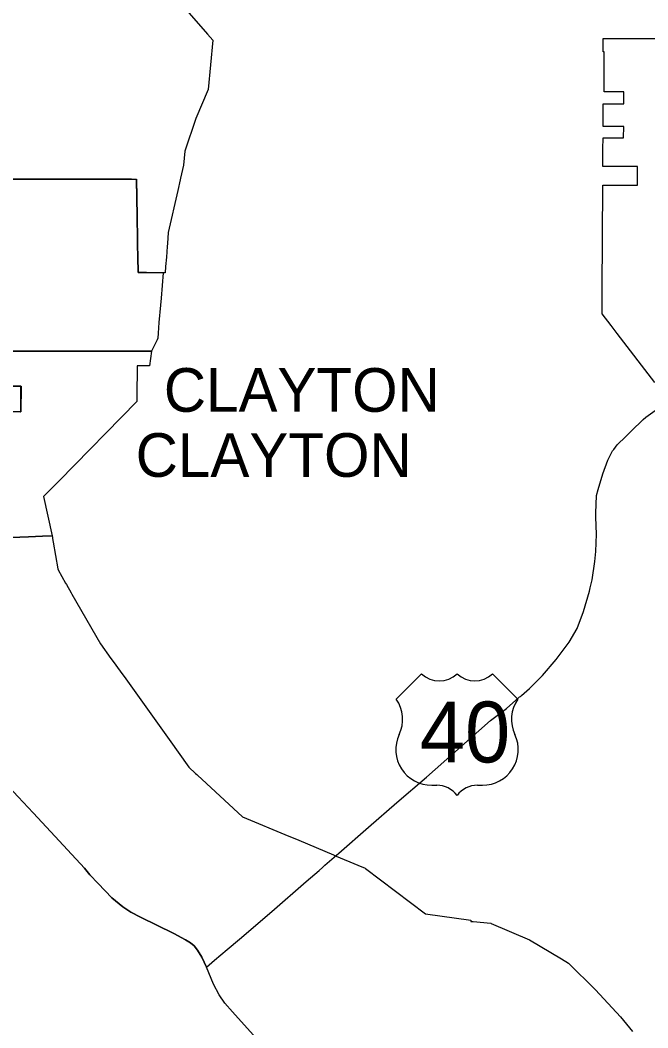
# Model space of a CAD drawing. Extents: x 0 to 34, y 0 to 22.
# Drawn here: x 4.8367 to 4.9522, y 15.7932 to 15.9787 of the extents above; entities that cross this region are included whole.
import ezdxf

# ---------------------------------------------------------------- set-up
doc = ezdxf.new("R2010")
doc.units = 0
for name, color, linetype in [('GM_X_Corporation', 7, 'Continuous'), ('GM_X_Corporation_Text', 7, 'Continuous'), ('GM_X_State_Route', 7, 'Continuous'), ('GM_X_US_Location', 7, 'Continuous'), ('GM_X_US_Route', 7, 'Continuous'), ('GM_X_US_Shield', 7, 'Continuous')]:
    doc.layers.add(name, color=color, linetype=linetype)

msp = doc.modelspace()

# ---------------------------------------------------------------- linework, layer by layer
at = {"layer": 'GM_X_Corporation'}
for points in [[(4.86732801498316, 15.98048374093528), (4.870376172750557, 15.977005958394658), (4.871194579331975, 15.976072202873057), (4.872133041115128, 15.975001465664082), (4.871292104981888, 15.965905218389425), (4.869025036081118, 15.960558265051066), (4.867015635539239, 15.954570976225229), (4.866730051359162, 15.951961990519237), (4.866198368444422, 15.949594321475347), (4.866121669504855, 15.949252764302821), (4.865683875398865, 15.94730306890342), (4.863947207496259, 15.939568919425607), (4.863789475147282, 15.937548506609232), (4.863745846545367, 15.936989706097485), (4.863596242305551, 15.935073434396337), (4.863461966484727, 15.93335351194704), (4.863369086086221, 15.93216379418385), (4.863229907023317, 15.932165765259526), (4.863014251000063, 15.932168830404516), (4.859974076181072, 15.93221248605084), (4.858384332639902, 15.932235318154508), (4.858335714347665, 15.935125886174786), (4.858325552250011, 15.935730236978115), (4.858309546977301, 15.936681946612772), (4.858282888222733, 15.938266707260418), (4.858210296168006, 15.942582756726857), (4.858096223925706, 15.94936529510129), (4.857178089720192, 15.949367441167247), (4.857005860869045, 15.949367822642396), (4.842103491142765, 15.949400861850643), (4.835353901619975, 15.949415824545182)], [(4.953444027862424, 15.912000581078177), (4.946545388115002, 15.920981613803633), (4.945430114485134, 15.922445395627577), (4.943764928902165, 15.92463092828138), (4.943765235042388, 15.924695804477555), (4.943779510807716, 15.927757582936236), (4.943785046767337, 15.928945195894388), (4.943875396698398, 15.94832243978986), (4.950272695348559, 15.94831126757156), (4.950289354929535, 15.951703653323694), (4.94389204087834, 15.951711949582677), (4.943907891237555, 15.954940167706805), (4.943917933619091, 15.956984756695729), (4.947715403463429, 15.956991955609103), (4.947723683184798, 15.959090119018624), (4.943928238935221, 15.95908292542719), (4.94393893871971, 15.961261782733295), (4.943948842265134, 15.963279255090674), (4.944113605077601, 15.963279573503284), (4.947731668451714, 15.96328642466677), (4.947740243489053, 15.963286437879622), (4.9477403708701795, 15.963318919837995), (4.947748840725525, 15.965465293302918), (4.944124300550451, 15.965458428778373), (4.94413105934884, 15.966834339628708), (4.944134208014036, 15.967475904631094), (4.9441441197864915, 15.969493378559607), (4.944120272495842, 15.972834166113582), (4.943975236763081, 15.972833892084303), (4.943964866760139, 15.975254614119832), (4.946785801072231, 15.97525996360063), (4.9477874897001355, 15.975261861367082), (4.9506039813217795, 15.975267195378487), (4.965187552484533, 15.975300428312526)], [(4.835353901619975, 15.949415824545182), (4.842103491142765, 15.949400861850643), (4.857005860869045, 15.949367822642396), (4.857178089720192, 15.949367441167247), (4.858096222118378, 15.949365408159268), (4.858210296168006, 15.942582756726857), (4.858282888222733, 15.938266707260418), (4.858309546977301, 15.936681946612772), (4.858325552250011, 15.935730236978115), (4.858335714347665, 15.935125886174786), (4.858384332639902, 15.932235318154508), (4.859974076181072, 15.93221248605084), (4.863014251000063, 15.932168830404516), (4.862641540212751, 15.927490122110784), (4.862538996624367, 15.926202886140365), (4.862204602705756, 15.923007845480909), (4.862080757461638, 15.921040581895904), (4.862022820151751, 15.920120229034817), (4.8618837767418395, 15.919837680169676), (4.86140467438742, 15.91886410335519), (4.860857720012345, 15.917752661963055), (4.85820128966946, 15.917755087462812), (4.854761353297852, 15.917758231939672), (4.838647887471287, 15.917772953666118), (4.836753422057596, 15.917774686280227), (4.834143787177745, 15.917777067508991)], [(4.834143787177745, 15.917777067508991), (4.836753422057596, 15.917774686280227), (4.838647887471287, 15.917772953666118), (4.854761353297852, 15.917758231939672), (4.85820128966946, 15.917755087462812), (4.860857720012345, 15.917752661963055), (4.8605043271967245, 15.91503645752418), (4.858202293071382, 15.915058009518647), (4.858149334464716, 15.909350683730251), (4.858146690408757, 15.909060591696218), (4.8581415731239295, 15.908499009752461), (4.843850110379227, 15.893888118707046), (4.841019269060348, 15.890994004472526), (4.842564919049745, 15.883763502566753), (4.840817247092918, 15.883692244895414), (4.838247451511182, 15.88358746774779), (4.833542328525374, 15.883395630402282)], [(4.833394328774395, 15.91131844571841), (4.836849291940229, 15.91129423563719), (4.836883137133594, 15.91129399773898), (4.8368578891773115, 15.906610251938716), (4.836762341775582, 15.90661091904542), (4.8336865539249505, 15.906632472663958)], [(4.8336865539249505, 15.906632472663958), (4.836762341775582, 15.90661091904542), (4.8368578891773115, 15.906610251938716), (4.836849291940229, 15.91129423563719), (4.833394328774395, 15.91131844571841)], [(4.833542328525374, 15.883395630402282), (4.838247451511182, 15.88358746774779), (4.84083844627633, 15.883693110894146), (4.842564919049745, 15.883763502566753), (4.84262610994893, 15.883477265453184), (4.842664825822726, 15.88329614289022), (4.842785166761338, 15.88261067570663), (4.843652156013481, 15.877672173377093), (4.843684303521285, 15.877489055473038), (4.845070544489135, 15.875064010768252), (4.8452040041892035, 15.874830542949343), (4.846079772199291, 15.873298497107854), (4.846217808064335, 15.87305702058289), (4.8514657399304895, 15.86387646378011), (4.851465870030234, 15.863876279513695), (4.853406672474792, 15.861202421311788), (4.85379304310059, 15.860670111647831), (4.855114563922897, 15.858849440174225), (4.856114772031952, 15.857471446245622), (4.857684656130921, 15.855308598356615), (4.858580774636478, 15.854051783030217), (4.86410747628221, 15.846300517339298), (4.867740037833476, 15.84120580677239), (4.8689862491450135, 15.840058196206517), (4.8692227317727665, 15.839840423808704), (4.869342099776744, 15.839730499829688), (4.877614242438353, 15.832097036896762), (4.886096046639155, 15.828527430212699), (4.886320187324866, 15.828433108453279), (4.887946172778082, 15.827748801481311), (4.894329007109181, 15.825062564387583), (4.894574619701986, 15.824959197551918), (4.894824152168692, 15.82485417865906), (4.89882862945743, 15.823168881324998), (4.900173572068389, 15.822602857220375), (4.900177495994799, 15.822601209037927), (4.900209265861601, 15.82257721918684), (4.900224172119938, 15.822565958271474), (4.911245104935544, 15.814243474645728), (4.919622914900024, 15.813044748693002), (4.91962313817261, 15.812825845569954), (4.920012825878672, 15.812810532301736), (4.923305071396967, 15.81248576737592), (4.923335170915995, 15.812472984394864), (4.9304133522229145, 15.809467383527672), (4.936288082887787, 15.805923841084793), (4.937571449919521, 15.805149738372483), (4.942506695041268, 15.80026118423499), (4.947116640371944, 15.79524555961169), (4.949320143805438, 15.792570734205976)]]:
    msp.add_lwpolyline(points, dxfattribs=at)
at = {"layer": 'GM_X_State_Route'}
for points in [[(4.864988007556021, 15.810628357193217), (4.858863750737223, 15.813592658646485), (4.857039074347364, 15.81452820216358), (4.855561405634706, 15.815516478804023), (4.853586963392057, 15.817147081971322), (4.851081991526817, 15.819793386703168), (4.849531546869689, 15.821406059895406), (4.848529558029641, 15.822596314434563), (4.845429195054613, 15.826009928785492), (4.842344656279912, 15.829329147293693), (4.839079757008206, 15.832797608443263), (4.836315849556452, 15.835725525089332), (4.834551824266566, 15.837624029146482), (4.833854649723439, 15.838495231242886), (4.833121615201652, 15.839420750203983), (4.832761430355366, 15.839953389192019), (4.831764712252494, 15.841528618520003), (4.830733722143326, 15.843108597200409), (4.828572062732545, 15.846547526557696), (4.825308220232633, 15.851501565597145), (4.824820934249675, 15.85229849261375)], [(4.870982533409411, 15.804437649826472), (4.870130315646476, 15.806261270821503), (4.8693550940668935, 15.807548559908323), (4.868681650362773, 15.808315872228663), (4.86801664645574, 15.808875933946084), (4.867131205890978, 15.809411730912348), (4.864988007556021, 15.810628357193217)], [(4.887960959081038, 15.782940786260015), (4.885214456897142, 15.785879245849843), (4.883214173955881, 15.788073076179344), (4.88224066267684, 15.789100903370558), (4.881530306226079, 15.789851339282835), (4.879577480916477, 15.791953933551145), (4.875763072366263, 15.796179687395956), (4.874326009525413, 15.79779869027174), (4.873300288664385, 15.799289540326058), (4.872257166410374, 15.801254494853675), (4.870982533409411, 15.804437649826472)]]:
    msp.add_lwpolyline(points, dxfattribs=at)
at = {"layer": 'GM_X_US_Route'}
for p, q in [((4.9287233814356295, 15.854240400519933), (4.928930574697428, 15.854421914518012)), ((4.9285852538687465, 15.85411939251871), (4.9287233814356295, 15.854240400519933)), ((4.872431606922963, 15.805666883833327), (4.874762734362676, 15.807644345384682)), ((4.870982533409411, 15.804437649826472), (4.872431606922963, 15.805666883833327))]:
    msp.add_line(p, q, dxfattribs=at)
for points in [[(4.9480976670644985, 15.902065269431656), (4.949072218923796, 15.903039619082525), (4.9513066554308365, 15.905178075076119), (4.9518002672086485, 15.905616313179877), (4.955004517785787, 15.907877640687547)], [(4.942624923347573, 15.887176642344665), (4.942622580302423, 15.88725830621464), (4.9426035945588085, 15.887911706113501), (4.94274229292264, 15.891174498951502), (4.943016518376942, 15.8922703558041), (4.943892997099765, 15.895175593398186), (4.944810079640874, 15.897668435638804), (4.94568708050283, 15.899422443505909), (4.945876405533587, 15.899662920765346), (4.9465498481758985, 15.90051777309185), (4.9480976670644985, 15.902065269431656)], [(4.9415652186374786, 15.874230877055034), (4.941895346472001, 15.875706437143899), (4.942431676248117, 15.879027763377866), (4.942620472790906, 15.88088354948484), (4.942713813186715, 15.88407356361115), (4.942624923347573, 15.887176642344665)], [(4.928930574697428, 15.854421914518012), (4.930380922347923, 15.855692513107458), (4.93281311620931, 15.858071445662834), (4.9352874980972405, 15.861030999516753), (4.937669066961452, 15.864185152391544), (4.939135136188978, 15.86674180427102), (4.940320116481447, 15.869852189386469), (4.941418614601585, 15.8735769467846), (4.9415652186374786, 15.874230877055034)], [(4.892308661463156, 15.82276885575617), (4.892750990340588, 15.82315320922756), (4.895311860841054, 15.825378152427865), (4.900806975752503, 15.830195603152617), (4.90600729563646, 15.834726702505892), (4.911434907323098, 15.83938383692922), (4.916799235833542, 15.844106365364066), (4.9232114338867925, 15.849780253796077), (4.926134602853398, 15.851971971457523), (4.9279091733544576, 15.853526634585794), (4.9285852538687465, 15.85411939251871)], [(4.824820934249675, 15.85229849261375), (4.825308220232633, 15.851501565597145), (4.828572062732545, 15.846547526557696), (4.830733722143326, 15.843108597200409), (4.831764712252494, 15.841528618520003), (4.832761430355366, 15.839953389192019), (4.833121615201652, 15.839420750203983), (4.833854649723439, 15.838495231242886), (4.834551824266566, 15.837624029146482), (4.836315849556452, 15.835725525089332), (4.839079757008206, 15.832797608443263), (4.842344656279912, 15.829329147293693), (4.845429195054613, 15.826009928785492), (4.848529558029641, 15.822596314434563), (4.849531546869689, 15.821406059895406), (4.851081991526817, 15.819793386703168), (4.853586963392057, 15.817147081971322), (4.855561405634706, 15.815516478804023), (4.857039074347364, 15.81452820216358), (4.858863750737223, 15.813592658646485), (4.864988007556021, 15.810628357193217)], [(4.874762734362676, 15.807644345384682), (4.877030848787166, 15.809568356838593), (4.883014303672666, 15.814667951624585), (4.889294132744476, 15.82014988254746), (4.891676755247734, 15.822219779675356), (4.892308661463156, 15.82276885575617)], [(4.864988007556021, 15.810628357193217), (4.867131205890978, 15.809411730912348), (4.86801664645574, 15.808875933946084), (4.868681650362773, 15.808315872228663), (4.8693550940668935, 15.807548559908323), (4.870130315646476, 15.806261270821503), (4.870982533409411, 15.804437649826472)]]:
    msp.add_lwpolyline(points, dxfattribs=at)
at = {"layer": 'GM_X_US_Shield'}
for p, q in [((4.910543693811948, 15.858400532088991), (4.9058815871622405, 15.85373842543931)), ((4.9282596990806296, 15.85373842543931), (4.923597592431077, 15.858400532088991)), ((4.912408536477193, 15.837887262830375), (4.913340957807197, 15.837887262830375)), ((4.920800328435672, 15.837887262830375), (4.921732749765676, 15.837887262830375))]:
    msp.add_line(p, q, dxfattribs=at)
for centre, radius, start, end in [((4.913807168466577, 15.861729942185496), 0.004662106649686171, 225.57299599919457, 314.4270040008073), ((4.920334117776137, 15.861729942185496), 0.004662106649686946, 225.57299599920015, 314.4270040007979), ((4.900535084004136, 15.84999463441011), 0.006526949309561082, 334.5471236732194, 35.000929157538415), ((4.933606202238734, 15.84999463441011), 0.006526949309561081, 144.99907084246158, 205.4528763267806), ((4.912335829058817, 15.844413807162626), 0.006526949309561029, 154.8319194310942, 270.63826363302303), ((4.921805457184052, 15.844413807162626), 0.006526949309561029, 269.36173636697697, 25.168080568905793), ((4.913340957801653, 15.833225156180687), 0.0046621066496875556, 36.86989764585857, 89.99999993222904), ((4.920800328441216, 15.833225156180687), 0.0046621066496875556, 90.00000006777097, 143.13010235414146)]:
    msp.add_arc(centre, radius, start, end, dxfattribs=at)

# ---------------------------------------------------------------- texts
at = {"layer": 'GM_X_Corporation_Text'}
for p in [(4.863132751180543, 15.906592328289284), (4.857957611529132, 15.894623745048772)]:
    msp.add_text('CLAYTON', height=0.008037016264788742, rotation=1.0000000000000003e-05, dxfattribs=at).set_placement(p)
at = {"layer": 'GM_X_US_Location'}
for s, p in [('0', (4.917064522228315, 15.847589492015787)), ('/', (4.917066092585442, 15.847589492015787))]:
    msp.add_text(s, height=1.6074032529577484e-05, dxfattribs=at).set_placement(p)
msp.add_text('40', height=1.6074032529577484e-05, rotation=1.0000000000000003e-05, dxfattribs=at).set_placement((4.913746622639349, 15.844262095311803))
at = {"layer": 'GM_X_US_Shield'}
msp.add_text('40', height=0.011189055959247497, dxfattribs=at).set_placement((4.910204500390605, 15.842083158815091))

doc.saveas('drawing.dxf')
